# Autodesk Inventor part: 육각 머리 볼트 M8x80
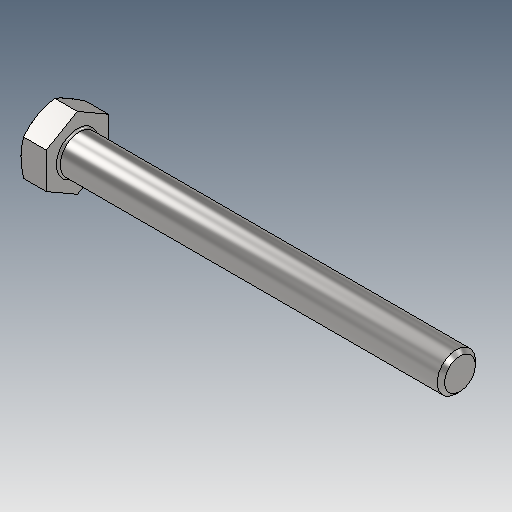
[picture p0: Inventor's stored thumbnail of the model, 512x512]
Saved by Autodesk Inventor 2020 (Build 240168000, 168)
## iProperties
Created: 2025-01
Part Number: 육각 머리 볼트 M8x80
Material: 강철, 연강
Description: 6각 머리 볼트 및 6각 머리 나사
Document SubType Name: Modeling
Designer: 1강의실14
Density: 7.85 g/cm^3
Appearance: 기본값
Author: jhkim
Sending System: Autodesk Inventor 2025
Preprocessor: ST-DEVELOPER v20
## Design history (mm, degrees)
feature "Solid1"
node "솔리드1"
